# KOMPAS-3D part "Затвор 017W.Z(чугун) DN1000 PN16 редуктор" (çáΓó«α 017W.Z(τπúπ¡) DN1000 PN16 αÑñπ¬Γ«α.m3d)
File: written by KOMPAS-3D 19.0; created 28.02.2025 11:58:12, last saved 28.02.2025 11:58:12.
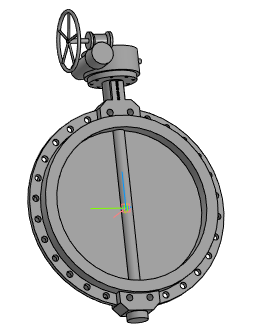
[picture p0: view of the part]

Document properties: Автор: Евгений; Полное имя файла: Затвор 017W.Z(чугун) DN1000 PN16 редуктор.a3d

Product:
- Part/product: Затвор 017W.Z(чугун) DN1000 PN16 редуктор
    Масса: 884.765

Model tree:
1. Операция без истории:1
